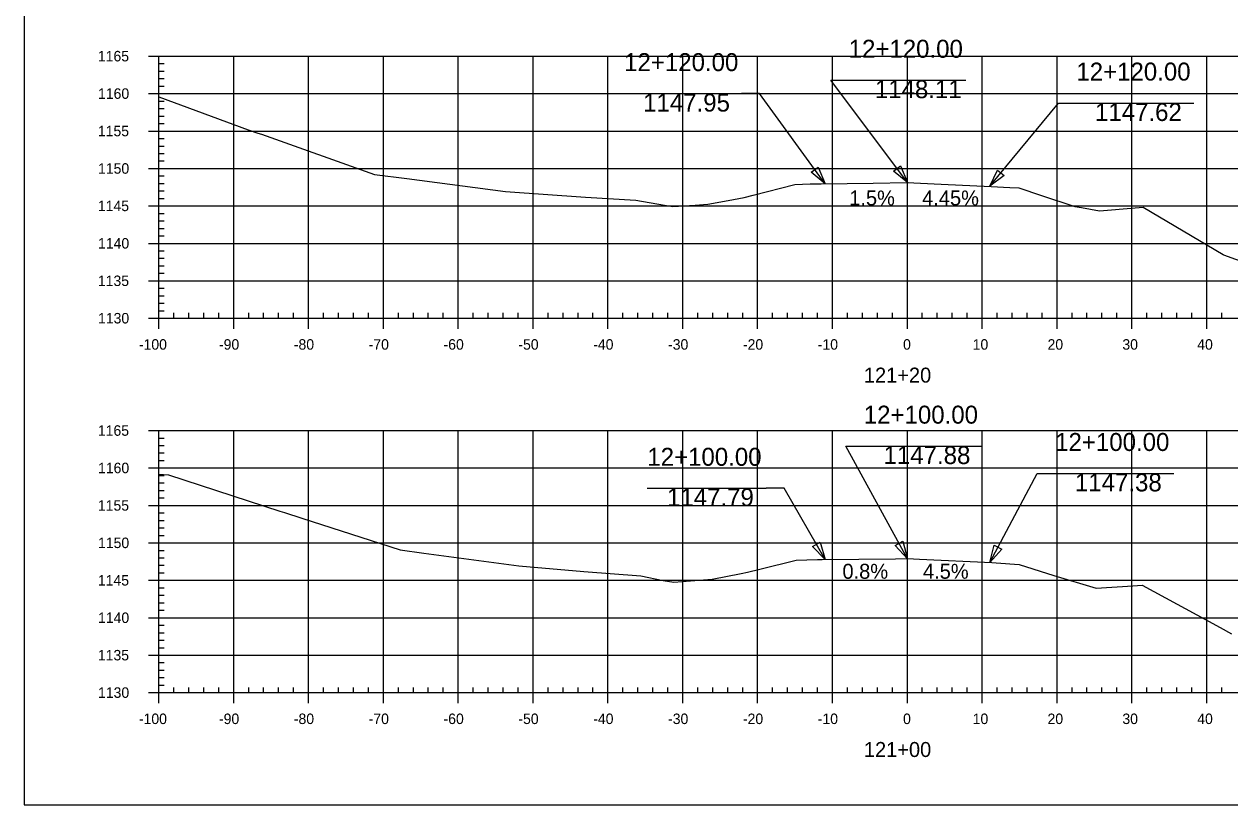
# Model space of a CAD drawing. Extents: x 688474 to 694748, y 765018 to 767373.
# Drawn here: x 690038.3 to 690199.4, y 765017.9 to 765122.1 of the extents above; entities that cross this region are included whole.
import ezdxf

# ---------------------------------------------------------------- set-up
doc = ezdxf.new("R2010")
doc.units = 0
for name, color, linetype in [('60', 7, 'Continuous'), ('Default', 7, 'Continuous'), ('R_Exist Surface', 7, 'Continuous'), ('R_Grid', 7, 'Continuous'), ('R_No Plot', 7, 'Continuous'), ('R_Xsect Slope', 7, 'Continuous')]:
    doc.layers.add(name, color=color, linetype=linetype)

msp = doc.modelspace()

# ---------------------------------------------------------------- linework, layer by layer
at = {"layer": '60'}
for p, q in [((690054.91, 765117.86), (690057.71, 765117.86)), ((690056.31, 765082.86), (690056.31, 765117.86)), ((690056.31, 765116.86), (690057.01, 765116.86)), ((690056.31, 765115.86), (690057.01, 765115.86)), ((690056.31, 765114.86), (690057.01, 765114.86)), ((690056.31, 765113.86), (690057.01, 765113.86)), ((690054.91, 765112.86), (690057.71, 765112.86)), ((690056.31, 765111.86), (690057.01, 765111.86)), ((690056.31, 765110.86), (690057.01, 765110.86)), ((690056.31, 765109.86), (690057.01, 765109.86)), ((690056.31, 765108.86), (690057.01, 765108.86)), ((690054.91, 765107.86), (690057.71, 765107.86)), ((690056.31, 765106.86), (690057.01, 765106.86)), ((690056.31, 765105.86), (690057.01, 765105.86)), ((690056.31, 765104.86), (690057.01, 765104.86)), ((690054.91, 765102.86), (690057.71, 765102.86)), ((690056.31, 765103.86), (690057.01, 765103.86)), ((690056.31, 765101.86), (690057.01, 765101.86)), ((690056.31, 765100.86), (690057.01, 765100.86)), ((690056.31, 765099.86), (690057.01, 765099.86)), ((690054.91, 765097.86), (690057.71, 765097.86)), ((690056.31, 765098.86), (690057.01, 765098.86)), ((690056.31, 765096.86), (690057.01, 765096.86)), ((690056.31, 765095.86), (690057.01, 765095.86)), ((690056.31, 765094.86), (690057.01, 765094.86)), ((690054.91, 765092.86), (690057.71, 765092.86)), ((690056.31, 765093.86), (690057.01, 765093.86)), ((690056.31, 765091.86), (690057.01, 765091.86)), ((690056.31, 765090.86), (690057.01, 765090.86)), ((690056.31, 765089.86), (690057.01, 765089.86)), ((690056.31, 765088.86), (690057.01, 765088.86)), ((690054.91, 765087.86), (690057.71, 765087.86)), ((690056.31, 765086.86), (690057.01, 765086.86)), ((690056.31, 765085.86), (690057.01, 765085.86)), ((690056.31, 765084.86), (690057.01, 765084.86)), ((690056.31, 765081.46), (690056.31, 765084.26)), ((690056.31, 765083.86), (690057.01, 765083.86)), ((690058.31, 765082.86), (690058.31, 765083.56)), ((690060.31, 765082.86), (690060.31, 765083.56)), ((690062.31, 765082.86), (690062.31, 765083.56)), ((690064.31, 765082.86), (690064.31, 765083.56)), ((690066.31, 765081.46), (690066.31, 765084.26)), ((690068.31, 765082.86), (690068.31, 765083.56)), ((690070.31, 765082.86), (690070.31, 765083.56)), ((690072.31, 765082.86), (690072.31, 765083.56)), ((690074.31, 765082.86), (690074.31, 765083.56)), ((690076.31, 765081.46), (690076.31, 765084.26)), ((690078.31, 765082.86), (690078.31, 765083.56)), ((690080.31, 765082.86), (690080.31, 765083.56)), ((690082.31, 765082.86), (690082.31, 765083.56)), ((690084.31, 765082.86), (690084.31, 765083.56)), ((690086.31, 765081.46), (690086.31, 765084.26)), ((690088.31, 765082.86), (690088.31, 765083.56)), ((690090.31, 765082.86), (690090.31, 765083.56)), ((690092.31, 765082.86), (690092.31, 765083.56)), ((690094.31, 765082.86), (690094.31, 765083.56)), ((690096.31, 765081.46), (690096.31, 765084.26)), ((690098.31, 765082.86), (690098.31, 765083.56)), ((690100.31, 765082.86), (690100.31, 765083.56)), ((690102.31, 765082.86), (690102.31, 765083.56)), ((690104.31, 765082.86), (690104.31, 765083.56)), ((690106.31, 765081.46), (690106.31, 765084.26)), ((690108.31, 765082.86), (690108.31, 765083.56)), ((690110.31, 765082.86), (690110.31, 765083.56)), ((690112.31, 765082.86), (690112.31, 765083.56)), ((690114.31, 765082.86), (690114.31, 765083.56)), ((690116.31, 765081.46), (690116.31, 765084.26)), ((690118.31, 765082.86), (690118.31, 765083.56)), ((690120.31, 765082.86), (690120.31, 765083.56)), ((690122.31, 765082.86), (690122.31, 765083.56)), ((690124.31, 765082.86), (690124.31, 765083.56)), ((690126.31, 765081.46), (690126.31, 765084.26)), ((690128.31, 765082.86), (690128.31, 765083.56)), ((690130.31, 765082.86), (690130.31, 765083.56)), ((690132.31, 765082.86), (690132.31, 765083.56)), ((690134.31, 765082.86), (690134.31, 765083.56)), ((690136.31, 765081.46), (690136.31, 765084.26)), ((690138.31, 765082.86), (690138.31, 765083.56)), ((690140.31, 765082.86), (690140.31, 765083.56)), ((690142.31, 765082.86), (690142.31, 765083.56)), ((690144.31, 765082.86), (690144.31, 765083.56)), ((690146.31, 765081.46), (690146.31, 765084.26)), ((690148.31, 765082.86), (690148.31, 765083.56)), ((690150.31, 765082.86), (690150.31, 765083.56)), ((690152.31, 765082.86), (690152.31, 765083.56)), ((690154.31, 765082.86), (690154.31, 765083.56)), ((690156.31, 765081.46), (690156.31, 765084.26)), ((690158.31, 765082.86), (690158.31, 765083.56)), ((690160.31, 765082.86), (690160.31, 765083.56)), ((690162.31, 765082.86), (690162.31, 765083.56)), ((690164.31, 765082.86), (690164.31, 765083.56)), ((690166.31, 765081.46), (690166.31, 765084.26)), ((690168.31, 765082.86), (690168.31, 765083.56)), ((690170.31, 765082.86), (690170.31, 765083.56)), ((690172.31, 765082.86), (690172.31, 765083.56)), ((690174.31, 765082.86), (690174.31, 765083.56)), ((690176.31, 765081.46), (690176.31, 765084.26)), ((690178.31, 765082.86), (690178.31, 765083.56)), ((690180.31, 765082.86), (690180.31, 765083.56)), ((690182.31, 765082.86), (690182.31, 765083.56)), ((690184.31, 765082.86), (690184.31, 765083.56)), ((690186.31, 765081.46), (690186.31, 765084.26)), ((690188.31, 765082.86), (690188.31, 765083.56)), ((690190.31, 765082.86), (690190.31, 765083.56)), ((690192.31, 765082.86), (690192.31, 765083.56)), ((690194.31, 765082.86), (690194.31, 765083.56)), ((690196.31, 765081.46), (690196.31, 765084.26)), ((690198.31, 765082.86), (690198.31, 765083.56)), ((690054.91, 765082.86), (690057.71, 765082.86)), ((690056.31, 765082.86), (690256.31, 765082.86)), ((690054.91, 765067.86), (690057.71, 765067.86)), ((690056.31, 765032.86), (690056.31, 765067.86)), ((690056.31, 765066.86), (690057.01, 765066.86)), ((690056.31, 765065.86), (690057.01, 765065.86)), ((690056.31, 765064.86), (690057.01, 765064.86)), ((690056.31, 765063.86), (690057.01, 765063.86)), ((690054.91, 765062.86), (690057.71, 765062.86)), ((690056.31, 765061.86), (690057.01, 765061.86)), ((690056.31, 765060.86), (690057.01, 765060.86)), ((690056.31, 765059.86), (690057.01, 765059.86)), ((690054.91, 765057.86), (690057.71, 765057.86)), ((690056.31, 765058.86), (690057.01, 765058.86)), ((690056.31, 765056.86), (690057.01, 765056.86)), ((690056.31, 765055.86), (690057.01, 765055.86)), ((690056.31, 765054.86), (690057.01, 765054.86)), ((690054.91, 765052.86), (690057.71, 765052.86)), ((690056.31, 765053.86), (690057.01, 765053.86)), ((690056.31, 765051.86), (690057.01, 765051.86)), ((690056.31, 765050.86), (690057.01, 765050.86)), ((690056.31, 765049.86), (690057.01, 765049.86)), ((690054.91, 765047.86), (690057.71, 765047.86)), ((690056.31, 765048.86), (690057.01, 765048.86)), ((690056.31, 765046.86), (690057.01, 765046.86)), ((690056.31, 765045.86), (690057.01, 765045.86)), ((690056.31, 765044.86), (690057.01, 765044.86)), ((690054.91, 765042.86), (690057.71, 765042.86)), ((690056.31, 765043.86), (690057.01, 765043.86)), ((690056.31, 765041.86), (690057.01, 765041.86)), ((690056.31, 765040.86), (690057.01, 765040.86)), ((690056.31, 765039.86), (690057.01, 765039.86)), ((690056.31, 765038.86), (690057.01, 765038.86)), ((690054.91, 765037.86), (690057.71, 765037.86)), ((690056.31, 765036.86), (690057.01, 765036.86)), ((690056.31, 765035.86), (690057.01, 765035.86)), ((690056.31, 765034.86), (690057.01, 765034.86)), ((690056.31, 765031.46), (690056.31, 765034.26)), ((690056.31, 765033.86), (690057.01, 765033.86)), ((690058.31, 765032.86), (690058.31, 765033.56)), ((690060.31, 765032.86), (690060.31, 765033.56)), ((690062.31, 765032.86), (690062.31, 765033.56)), ((690064.31, 765032.86), (690064.31, 765033.56)), ((690066.31, 765031.46), (690066.31, 765034.26)), ((690068.31, 765032.86), (690068.31, 765033.56)), ((690070.31, 765032.86), (690070.31, 765033.56)), ((690072.31, 765032.86), (690072.31, 765033.56)), ((690074.31, 765032.86), (690074.31, 765033.56)), ((690076.31, 765031.46), (690076.31, 765034.26)), ((690078.31, 765032.86), (690078.31, 765033.56)), ((690080.31, 765032.86), (690080.31, 765033.56)), ((690082.31, 765032.86), (690082.31, 765033.56)), ((690084.31, 765032.86), (690084.31, 765033.56)), ((690086.31, 765031.46), (690086.31, 765034.26)), ((690088.31, 765032.86), (690088.31, 765033.56)), ((690090.31, 765032.86), (690090.31, 765033.56)), ((690092.31, 765032.86), (690092.31, 765033.56)), ((690094.31, 765032.86), (690094.31, 765033.56)), ((690096.31, 765031.46), (690096.31, 765034.26)), ((690098.31, 765032.86), (690098.31, 765033.56)), ((690100.31, 765032.86), (690100.31, 765033.56)), ((690102.31, 765032.86), (690102.31, 765033.56)), ((690104.31, 765032.86), (690104.31, 765033.56)), ((690106.31, 765031.46), (690106.31, 765034.26)), ((690108.31, 765032.86), (690108.31, 765033.56)), ((690110.31, 765032.86), (690110.31, 765033.56)), ((690112.31, 765032.86), (690112.31, 765033.56)), ((690114.31, 765032.86), (690114.31, 765033.56)), ((690116.31, 765031.46), (690116.31, 765034.26)), ((690118.31, 765032.86), (690118.31, 765033.56)), ((690120.31, 765032.86), (690120.31, 765033.56)), ((690122.31, 765032.86), (690122.31, 765033.56)), ((690124.31, 765032.86), (690124.31, 765033.56)), ((690126.31, 765031.46), (690126.31, 765034.26)), ((690128.31, 765032.86), (690128.31, 765033.56)), ((690130.31, 765032.86), (690130.31, 765033.56)), ((690132.31, 765032.86), (690132.31, 765033.56)), ((690134.31, 765032.86), (690134.31, 765033.56)), ((690136.31, 765031.46), (690136.31, 765034.26)), ((690138.31, 765032.86), (690138.31, 765033.56)), ((690140.31, 765032.86), (690140.31, 765033.56)), ((690142.31, 765032.86), (690142.31, 765033.56)), ((690144.31, 765032.86), (690144.31, 765033.56)), ((690146.31, 765031.46), (690146.31, 765034.26)), ((690148.31, 765032.86), (690148.31, 765033.56)), ((690150.31, 765032.86), (690150.31, 765033.56)), ((690152.31, 765032.86), (690152.31, 765033.56)), ((690154.31, 765032.86), (690154.31, 765033.56)), ((690156.31, 765031.46), (690156.31, 765034.26)), ((690158.31, 765032.86), (690158.31, 765033.56)), ((690160.31, 765032.86), (690160.31, 765033.56)), ((690162.31, 765032.86), (690162.31, 765033.56)), ((690164.31, 765032.86), (690164.31, 765033.56)), ((690166.31, 765031.46), (690166.31, 765034.26)), ((690168.31, 765032.86), (690168.31, 765033.56)), ((690170.31, 765032.86), (690170.31, 765033.56)), ((690172.31, 765032.86), (690172.31, 765033.56)), ((690174.31, 765032.86), (690174.31, 765033.56)), ((690176.31, 765031.46), (690176.31, 765034.26)), ((690178.31, 765032.86), (690178.31, 765033.56)), ((690180.31, 765032.86), (690180.31, 765033.56)), ((690182.31, 765032.86), (690182.31, 765033.56)), ((690184.31, 765032.86), (690184.31, 765033.56)), ((690186.31, 765031.46), (690186.31, 765034.26)), ((690188.31, 765032.86), (690188.31, 765033.56)), ((690190.31, 765032.86), (690190.31, 765033.56)), ((690192.31, 765032.86), (690192.31, 765033.56)), ((690194.31, 765032.86), (690194.31, 765033.56)), ((690196.31, 765031.46), (690196.31, 765034.26)), ((690198.31, 765032.86), (690198.31, 765033.56)), ((690054.91, 765032.86), (690057.71, 765032.86)), ((690056.31, 765032.86), (690256.31, 765032.86))]:
    msp.add_line(p, q, dxfattribs=at)
at = {"layer": 'R_Exist Surface'}
for p, q in [((690148.47, 765114.65), (690164.14, 765114.65)), ((690118.47, 765112.86), (690134.14, 765112.86)), ((690178.89, 765111.6), (690194.57, 765111.6)), ((690150.49, 765065.78), (690166.35, 765065.78)), ((690176.06, 765062.13), (690191.92, 765062.13)), ((690121.57, 765060.15), (690137.44, 765060.15))]:
    msp.add_line(p, q, dxfattribs=at)
for points in [[(690156.31, 765100.98), (690146.07, 765114.65), (690148.47, 765114.65)], [(690056.31, 765112.42), (690068.22, 765108.04), (690069.52, 765107.58), (690070, 765107.42), (690085.1, 765102.07), (690089.44, 765101.5), (690102.62, 765099.8), (690113.31, 765099.04), (690120.05, 765098.63), (690123.88, 765097.95), (690124.98, 765097.78), (690127.94, 765097.98), (690129.67, 765098.11), (690132.35, 765098.6), (690134.49, 765098.99), (690135.73, 765099.31), (690141.29, 765100.74), (690143.33, 765100.79), (690144.81, 765100.81), (690151.76, 765100.9), (690156.25, 765100.98), (690160.84, 765100.78), (690167.5, 765100.47), (690169.99, 765100.33), (690171.21, 765100.26), (690174.22, 765099.26), (690178.68, 765097.8), (690179.58, 765097.64), (690182, 765097.18), (690186.77, 765097.61), (690187.81, 765097.69), (690198.5, 765091.35), (690198.57, 765091.31), (690198.57, 765091.31), (690203.36, 765089.6)], [(690145.31, 765100.82), (690136.54, 765112.86), (690134.14, 765112.86)], [(690167.31, 765100.48), (690176.49, 765111.6), (690178.89, 765111.6)], [(690156.31, 765050.74), (690148.09, 765065.78), (690150.49, 765065.78)], [(690167.31, 765050.24), (690173.66, 765062.13), (690176.06, 765062.13)], [(690056.31, 765062.02), (690057.58, 765061.93), (690072.48, 765057.11), (690073.08, 765056.9), (690075.4, 765056.14), (690088.56, 765051.93), (690091.72, 765051.49), (690104.4, 765049.8), (690113.08, 765049.04), (690120.72, 765048.47), (690123.68, 765047.85), (690125.1, 765047.6), (690127.35, 765047.77), (690130.24, 765047.99), (690134.11, 765048.76), (690134.94, 765048.93), (690136.58, 765049.33), (690141.46, 765050.54), (690144.32, 765050.63), (690144.91, 765050.65), (690154.72, 765050.72), (690156.34, 765050.75), (690157.94, 765050.67), (690167.59, 765050.23), (690168.19, 765050.19), (690171.27, 765049.99), (690175.89, 765048.5), (690181.54, 765046.82), (690186.42, 765047.13), (690187.68, 765047.23), (690198.1, 765041.55), (690199.62, 765040.73)], [(690145.31, 765050.65), (690139.84, 765060.15), (690137.44, 765060.15)]]:
    msp.add_lwpolyline(points, dxfattribs=at)
for points in [[(690145.31, 765100.82), (690143.46, 765102.36), (690144.41, 765103.04)], [(690156.31, 765100.98), (690154.44, 765102.49), (690155.38, 765103.19)], [(690167.31, 765100.48), (690168.34, 765102.65), (690169.24, 765101.91)], [(690145.31, 765050.65), (690143.64, 765052.38), (690144.65, 765052.96)], [(690156.31, 765050.74), (690154.68, 765052.51), (690155.7, 765053.07)], [(690167.31, 765050.24), (690167.89, 765052.57), (690168.92, 765052.02)]]:
    msp.add_lwpolyline(points, close=True, dxfattribs=at)
at = {"layer": 'R_Grid'}
for p, q in [((690056.31, 765117.86), (690256.31, 765117.86)), ((690056.31, 765082.86), (690056.31, 765117.86)), ((690066.31, 765082.86), (690066.31, 765117.86)), ((690076.31, 765082.86), (690076.31, 765117.86)), ((690086.31, 765082.86), (690086.31, 765117.86)), ((690096.31, 765082.86), (690096.31, 765117.86)), ((690106.31, 765082.86), (690106.31, 765117.86)), ((690116.31, 765082.86), (690116.31, 765117.86)), ((690126.31, 765082.86), (690126.31, 765117.86)), ((690136.31, 765082.86), (690136.31, 765117.86)), ((690146.31, 765082.86), (690146.31, 765117.86)), ((690156.31, 765082.86), (690156.31, 765117.86)), ((690166.31, 765082.86), (690166.31, 765117.86)), ((690176.31, 765082.86), (690176.31, 765117.86)), ((690186.31, 765082.86), (690186.31, 765117.86)), ((690196.31, 765082.86), (690196.31, 765117.86)), ((690056.31, 765112.86), (690256.31, 765112.86)), ((690056.31, 765107.86), (690256.31, 765107.86)), ((690056.31, 765102.86), (690256.31, 765102.86)), ((690056.31, 765097.86), (690256.31, 765097.86)), ((690056.31, 765092.86), (690256.31, 765092.86)), ((690056.31, 765087.86), (690256.31, 765087.86)), ((690056.31, 765082.86), (690256.31, 765082.86)), ((690056.31, 765067.86), (690256.31, 765067.86)), ((690056.31, 765032.86), (690056.31, 765067.86)), ((690066.31, 765032.86), (690066.31, 765067.86)), ((690076.31, 765032.86), (690076.31, 765067.86)), ((690086.31, 765032.86), (690086.31, 765067.86)), ((690096.31, 765032.86), (690096.31, 765067.86)), ((690106.31, 765032.86), (690106.31, 765067.86)), ((690116.31, 765032.86), (690116.31, 765067.86)), ((690126.31, 765032.86), (690126.31, 765067.86)), ((690136.31, 765032.86), (690136.31, 765067.86)), ((690146.31, 765032.86), (690146.31, 765067.86)), ((690156.31, 765032.86), (690156.31, 765067.86)), ((690166.31, 765032.86), (690166.31, 765067.86)), ((690176.31, 765032.86), (690176.31, 765067.86)), ((690186.31, 765032.86), (690186.31, 765067.86)), ((690196.31, 765032.86), (690196.31, 765067.86)), ((690056.31, 765062.86), (690256.31, 765062.86)), ((690056.31, 765057.86), (690256.31, 765057.86)), ((690056.31, 765052.86), (690256.31, 765052.86)), ((690056.31, 765047.86), (690256.31, 765047.86)), ((690056.31, 765042.86), (690256.31, 765042.86)), ((690056.31, 765037.86), (690256.31, 765037.86)), ((690056.31, 765032.86), (690256.31, 765032.86))]:
    msp.add_line(p, q, dxfattribs=at)
at = {"layer": 'R_No Plot'}
msp.add_lwpolyline([(690038.31, 765017.86), (690354.49, 765017.86), (690354.49, 765223.32), (690038.31, 765223.32)], close=True, dxfattribs=at)

# ---------------------------------------------------------------- texts
at = {"layer": '60'}
for s, height, p in [('1165', 1.4, (690048.16, 765117.16)), ('1160', 1.4, (690048.18, 765112.16)), ('1155', 1.4, (690048.16, 765107.16)), ('1150', 1.4, (690048.18, 765102.16)), ('1145', 1.4, (690048.16, 765097.16)), ('1140', 1.4, (690048.18, 765092.16)), ('1135', 1.4, (690048.16, 765087.16)), ('1130', 1.4, (690048.18, 765082.16)), ('-100', 1.4, (690053.64, 765078.66)), ('-90', 1.4, (690064.34, 765078.66)), ('-80', 1.4, (690074.34, 765078.66)), ('-70', 1.4, (690084.34, 765078.66)), ('-60', 1.4, (690094.34, 765078.66)), ('-50', 1.4, (690104.34, 765078.66)), ('-40', 1.4, (690114.34, 765078.66)), ('-30', 1.4, (690124.34, 765078.66)), ('-20', 1.4, (690134.34, 765078.66)), ('-10', 1.4, (690144.34, 765078.66)), ('0', 1.4, (690155.74, 765078.66)), ('10', 1.4, (690165.04, 765078.66)), ('20', 1.4, (690175.04, 765078.66)), ('30', 1.4, (690185.04, 765078.66)), ('40', 1.4, (690195.04, 765078.66)), ('121+20', 2, (690150.5, 765074.26)), ('1165', 1.4, (690048.16, 765067.16)), ('1160', 1.4, (690048.18, 765062.16)), ('1155', 1.4, (690048.16, 765057.16)), ('1150', 1.4, (690048.18, 765052.16)), ('1145', 1.4, (690048.16, 765047.16)), ('1140', 1.4, (690048.18, 765042.16)), ('1135', 1.4, (690048.16, 765037.16)), ('1130', 1.4, (690048.18, 765032.16)), ('-100', 1.4, (690053.64, 765028.66)), ('-90', 1.4, (690064.34, 765028.66)), ('-80', 1.4, (690074.34, 765028.66)), ('-70', 1.4, (690084.34, 765028.66)), ('-60', 1.4, (690094.34, 765028.66)), ('-50', 1.4, (690104.34, 765028.66)), ('-40', 1.4, (690114.34, 765028.66)), ('-30', 1.4, (690124.34, 765028.66)), ('-20', 1.4, (690134.34, 765028.66)), ('-10', 1.4, (690144.34, 765028.66)), ('0', 1.4, (690155.74, 765028.66)), ('10', 1.4, (690165.04, 765028.66)), ('20', 1.4, (690175.04, 765028.66)), ('30', 1.4, (690185.04, 765028.66)), ('40', 1.4, (690195.04, 765028.66)), ('121+00', 2, (690150.5, 765024.26))]:
    msp.add_text(s, height=height, dxfattribs=at).set_placement(p)
at = {"layer": 'Default'}
for s, p in [('1.5%', (690148.55, 765097.92)), ('4.45%', (690158.29, 765097.92)), ('0.8%', (690147.64, 765048.06)), ('4.5%', (690158.4, 765048.06))]:
    msp.add_text(s, height=2, dxfattribs=at).set_placement(p)
at = {"layer": 'R_Xsect Slope'}
for s, p in [('12+120.00', (690148.47, 765117.65)), ('12+120.00', (690118.47, 765115.86)), ('12+120.00', (690178.89, 765114.6)), ('1148.11', (690151.97, 765112.25)), ('1147.95', (690121.01, 765110.46)), ('1147.62', (690181.38, 765109.2)), ('12+100.00', (690150.49, 765068.78)), ('12+100.00', (690176.06, 765065.13)), ('12+100.00', (690121.57, 765063.15)), ('1147.88', (690153.13, 765063.38)), ('1147.38', (690178.7, 765059.73)), ('1147.79', (690124.2, 765057.75))]:
    msp.add_text(s, height=2.4, dxfattribs=at).set_placement(p)

doc.saveas('drawing.dxf')
